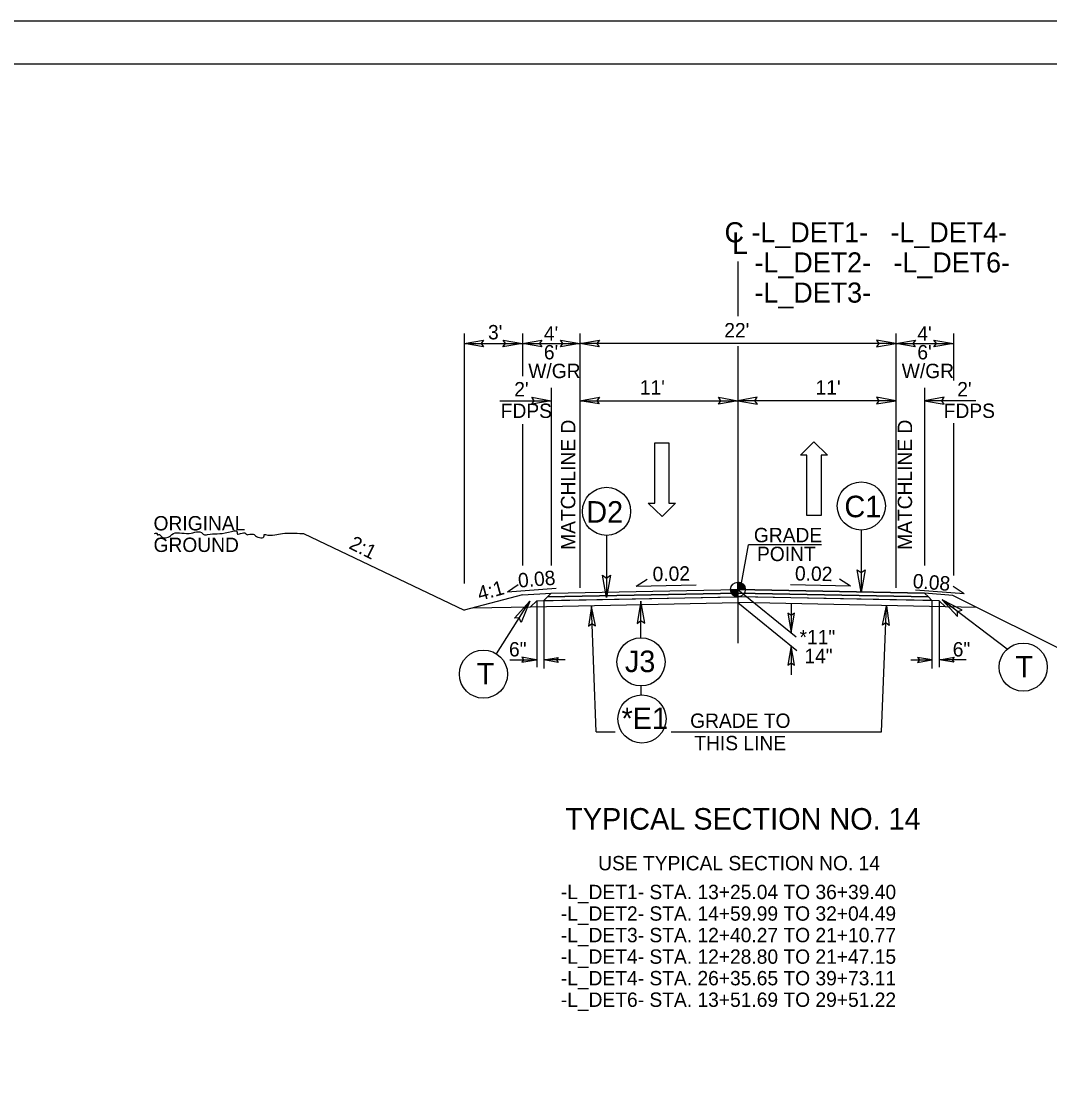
# Model space of a CAD drawing. Extents: x 18938 to 19565, y 6931 to 7973.
# Drawn here: x 19226.8 to 19298.4, y 7150.9 to 7224.2 of the extents above; entities that cross this region are included whole.
import ezdxf

# ---------------------------------------------------------------- set-up
doc = ezdxf.new("R2010")
doc.units = 0
for name, color, linetype in [('Old_Level_11', 7, 'Continuous'), ('Old_Level_2', 7, 'Continuous'), ('Old_Level_3', 7, 'Continuous'), ('Prop Dimension', 7, 'Continuous'), ('Prop Pavement Schedule Description CELL', 7, 'Continuous'), ('Prop Shade Medium', 7, 'Continuous'), ('Prop Terminator CELL', 7, 'Continuous'), ('Sheet Block Title CELL', 7, 'Continuous'), ('Sheet Data Field CELL', 7, 'Continuous'), ('Sheet Plot Border Outside CELL', 7, 'Continuous'), ('Sheet Typical CELL', 7, 'Continuous'), ('Typical Curb CELL', 7, 'Continuous'), ('Typical Detail Wedge1 CELL', 7, 'Continuous'), ('Typical Detail Wedge2 CELL', 7, 'Continuous'), ('Typical Detail Wedge3 CELL', 7, 'Continuous'), ('Typical Hinge Slope Arterial CELL', 7, 'Continuous'), ('Typical Pavement Slope Information CELL', 7, 'Continuous'), ('Typical Shoulder Slope Information CELL', 7, 'Continuous'), ('Typical Terminator CELL', 7, 'Continuous'), ('Typical Text General CELL', 7, 'Continuous'), ('Typical Text Grade Point CELL', 7, 'Continuous'), ('Typical Text ID Circle CELL', 7, 'Continuous'), ('Typical Text Label CELL', 7, 'Continuous')]:
    doc.layers.add(name, color=color, linetype=linetype)

msp = doc.modelspace()

# ---------------------------------------------------------------- linework, layer by layer
at = {"layer": 'Old_Level_3'}
for p, q in [((19260.819, 7179.737), (19262.657, 7179.733)), ((19260.819, 7179.737), (19262.657, 7179.733)), ((19264.664, 7179.722), (19263.187, 7179.722)), ((19264.664, 7179.722), (19263.187, 7179.722)), ((19288.731, 7179.722), (19290.208, 7179.722)), ((19292.576, 7179.737), (19290.738, 7179.733))]:
    msp.add_line(p, q, dxfattribs=at)
at = {"layer": 'Prop Dimension'}
msp.add_lwpolyline([(19155.167, 7077.771), (19382.434, 7077.771), (19382.434, 7224.204), (19155.167, 7224.204)], close=True, dxfattribs=at)
at = {"layer": 'Prop Pavement Schedule Description CELL'}
for p, q in [((19261.697, 7184.244), (19263.697, 7184.366)), ((19262.687, 7183.846), (19276.442, 7184.121)), ((19262.687, 7183.846), (19276.442, 7184.121)), ((19263.442, 7184.111), (19276.697, 7184.376)), ((19263.442, 7184.111), (19263.697, 7184.366)), ((19263.697, 7184.366), (19276.698, 7184.626)), ((19289.697, 7184.366), (19276.697, 7184.626)), ((19289.953, 7184.111), (19276.697, 7184.376)), ((19290.708, 7183.846), (19276.953, 7184.121)), ((19291.66, 7184.209), (19289.697, 7184.366)), ((19289.953, 7184.111), (19289.697, 7184.366)), ((19308.052, 7176.014), (19291.66, 7184.209)), ((19258.223, 7183.341), (19262.254, 7183.421)), ((19262.254, 7183.421), (19262.687, 7183.846)), ((19262.254, 7183.421), (19262.687, 7183.846)), ((19262.254, 7183.421), (19276.711, 7183.711)), ((19291.141, 7183.421), (19276.684, 7183.711)), ((19291.141, 7183.421), (19290.708, 7183.846)), ((19293.323, 7183.378), (19291.141, 7183.421))]:
    msp.add_line(p, q, dxfattribs=at)
at = {"layer": 'Prop Shade Medium'}
for p in [(19246.456, 7188.533), (19261.697, 7184.244)]:
    msp.add_line(p, (19257.631, 7183.187), dxfattribs=at)
at = {"layer": 'Sheet Block Title CELL'}
for p, q in [((19263.187, 7183.856), (19276.697, 7184.126)), ((19263.187, 7183.856), (19276.697, 7184.126)), ((19263.442, 7184.111), (19263.187, 7183.856)), ((19263.442, 7184.111), (19263.187, 7183.856)), ((19276.697, 7184.376), (19263.442, 7184.111)), ((19276.697, 7184.376), (19263.442, 7184.111)), ((19276.697, 7184.126), (19276.697, 7184.376)), ((19276.697, 7184.376), (19289.953, 7184.111)), ((19276.698, 7184.126), (19276.697, 7184.376)), ((19276.697, 7184.126), (19276.697, 7184.376)), ((19290.208, 7183.856), (19276.698, 7184.126)), ((19289.953, 7184.111), (19290.208, 7183.856))]:
    msp.add_line(p, q, dxfattribs=at)
at = {"layer": 'Sheet Data Field CELL'}
for points in [[(19258.981, 7201.521), (19257.631, 7201.753), (19258.988, 7201.993), (19258.816, 7201.753)], [(19260.347, 7201.986), (19261.697, 7201.753), (19260.34, 7201.513), (19260.512, 7201.753)], [(19263.047, 7201.521), (19261.697, 7201.753), (19263.055, 7201.993), (19262.882, 7201.753)], [(19264.347, 7201.986), (19265.697, 7201.753), (19264.34, 7201.513), (19264.512, 7201.753)], [(19267.047, 7201.521), (19265.697, 7201.753), (19267.055, 7201.993), (19266.882, 7201.753)], [(19286.347, 7201.521), (19287.697, 7201.753), (19286.34, 7201.993), (19286.512, 7201.753)], [(19289.047, 7201.521), (19287.697, 7201.753), (19289.055, 7201.993), (19288.882, 7201.753)], [(19290.347, 7201.986), (19291.697, 7201.753), (19290.34, 7201.513), (19290.512, 7201.753)], [(19262.347, 7198.007), (19263.697, 7197.774), (19262.34, 7197.534), (19262.512, 7197.774)], [(19267.047, 7197.542), (19265.697, 7197.774), (19267.055, 7198.014), (19266.882, 7197.774)], [(19275.347, 7198.007), (19276.697, 7197.774), (19275.34, 7197.534), (19275.512, 7197.774)], [(19278.047, 7198.007), (19276.697, 7197.774), (19278.055, 7197.534), (19277.882, 7197.774)], [(19286.347, 7197.542), (19287.697, 7197.774), (19286.34, 7198.014), (19286.512, 7197.774)], [(19291.047, 7198.007), (19289.697, 7197.774), (19291.055, 7197.534), (19290.882, 7197.774)], [(19266.773, 7182.101), (19266.495, 7183.443), (19266.301, 7182.078), (19266.535, 7182.259)], [(19286.764, 7182.148), (19287.042, 7183.49), (19287.236, 7182.125), (19287.002, 7182.305)], [(19280.174, 7182.972), (19280.407, 7181.622), (19280.647, 7182.979), (19280.407, 7182.807)], [(19280.639, 7179.356), (19280.407, 7180.706), (19280.167, 7179.348), (19280.407, 7179.521)]]:
    msp.add_lwpolyline(points, close=True, dxfattribs=at)
at = {"layer": 'Sheet Typical CELL'}
for p, q in [((19257.631, 7202.445), (19257.631, 7185.054)), ((19261.697, 7202.445), (19261.697, 7199.487)), ((19265.697, 7202.445), (19265.697, 7184.739)), ((19287.697, 7202.445), (19287.697, 7184.739)), ((19291.697, 7202.445), (19291.697, 7199.174)), ((19257.631, 7201.753), (19261.697, 7201.753)), ((19261.697, 7201.753), (19265.697, 7201.753)), ((19287.697, 7201.753), (19265.697, 7201.753)), ((19287.697, 7201.753), (19291.697, 7201.753)), ((19263.697, 7198.677), (19263.697, 7186.297)), ((19289.697, 7198.677), (19289.697, 7186.297)), ((19260.126, 7197.774), (19263.697, 7197.774)), ((19265.697, 7197.774), (19276.697, 7197.774)), ((19287.697, 7197.774), (19276.697, 7197.774)), ((19293.269, 7197.774), (19289.697, 7197.774)), ((19261.697, 7196.132), (19261.697, 7186.297)), ((19291.697, 7196.204), (19291.697, 7185.594)), ((19276.698, 7184.626), (19280.753, 7181.342)), ((19262.687, 7183.846), (19262.687, 7179.226)), ((19262.687, 7183.846), (19262.687, 7179.226)), ((19263.187, 7183.856), (19263.187, 7179.125)), ((19263.187, 7183.856), (19263.187, 7179.125)), ((19266.836, 7174.714), (19266.495, 7183.443)), ((19276.698, 7183.71), (19280.803, 7180.385)), ((19280.407, 7183.666), (19280.407, 7181.622)), ((19286.697, 7174.714), (19287.04, 7183.503)), ((19290.208, 7183.856), (19290.208, 7179.125)), ((19290.708, 7183.846), (19290.708, 7179.226)), ((19280.407, 7180.706), (19280.407, 7178.682)), ((19269.949, 7177.91), (19269.949, 7177.29)), ((19266.836, 7174.714), (19268.151, 7174.714)), ((19272.044, 7174.714), (19286.697, 7174.714))]:
    msp.add_line(p, q, dxfattribs=at)
at = {"layer": 'Typical Curb CELL'}
msp.add_spline([(19236.091, 7188.533), (19236.263, 7188.533), (19236.263, 7188.447), (19236.434, 7188.447), (19236.52, 7188.361), (19237.205, 7188.361), (19237.29, 7188.447), (19238.49, 7188.533), (19239.432, 7188.533), (19239.517, 7188.447), (19239.775, 7188.447), (19241.231, 7188.618), (19241.83, 7188.618), (19241.83, 7188.533), (19242.43, 7188.533), (19242.515, 7188.447), (19242.601, 7188.447), (19243.029, 7188.447), (19243.115, 7188.361), (19243.714, 7188.361), (19243.714, 7188.447), (19243.8, 7188.447), (19244.999, 7188.533), (19246.37, 7188.533), (19246.456, 7188.533)], degree=3, dxfattribs=at)
at = {"layer": 'Typical Detail Wedge1 CELL'}
for p, q in [((19276.698, 7184.626), (19276.698, 7185.138)), ((19276.185, 7184.626), (19276.698, 7184.626)), ((19276.697, 7184.114), (19276.698, 7184.626)), ((19276.698, 7184.626), (19276.697, 7184.114)), ((19277.209, 7184.626), (19276.698, 7184.626))]:
    msp.add_line(p, q, dxfattribs=at)
for points in [[(19276.702, 7185.138), (19276.702, 7185.138), (19276.702, 7184.626)], [(19276.713, 7185.138), (19276.713, 7184.626)], [(19276.723, 7185.138), (19276.723, 7184.626)], [(19276.733, 7185.137), (19276.733, 7184.626)], [(19276.744, 7185.136), (19276.744, 7184.626)], [(19276.754, 7185.135), (19276.754, 7184.626)], [(19276.764, 7185.134), (19276.764, 7184.626)], [(19276.774, 7185.133), (19276.774, 7184.626)], [(19276.785, 7185.131), (19276.784, 7184.626)], [(19276.795, 7185.129), (19276.795, 7184.626)], [(19276.805, 7185.127), (19276.805, 7184.626)], [(19276.815, 7185.124), (19276.815, 7184.626)], [(19276.826, 7185.122), (19276.825, 7184.626)], [(19276.836, 7185.119), (19276.836, 7184.626)], [(19276.846, 7185.116), (19276.846, 7184.626)], [(19276.856, 7185.113), (19276.856, 7184.626)], [(19276.867, 7185.11), (19276.866, 7184.626)], [(19276.877, 7185.106), (19276.876, 7184.626)], [(19276.887, 7185.102), (19276.887, 7184.626)], [(19276.897, 7185.098), (19276.897, 7184.626)], [(19276.907, 7185.093), (19276.907, 7184.626)], [(19276.918, 7185.089), (19276.918, 7184.626)], [(19276.928, 7185.084), (19276.928, 7184.626)], [(19276.938, 7185.078), (19276.938, 7184.626)], [(19276.949, 7185.073), (19276.948, 7184.626)], [(19276.959, 7185.067), (19276.959, 7184.626)], [(19276.969, 7185.061), (19276.969, 7184.626)], [(19276.979, 7185.054), (19276.979, 7184.626)], [(19276.989, 7185.047), (19276.989, 7184.626)], [(19277, 7185.04), (19277, 7184.626)], [(19277.01, 7185.032), (19277.01, 7184.626)], [(19277.02, 7185.024), (19277.02, 7184.626)], [(19277.03, 7185.015), (19277.03, 7184.626)], [(19277.041, 7185.006), (19277.04, 7184.626)], [(19277.051, 7184.997), (19277.051, 7184.626)], [(19277.061, 7184.987), (19277.061, 7184.626)], [(19277.071, 7184.976), (19277.071, 7184.626)], [(19277.081, 7184.965), (19277.081, 7184.626)], [(19277.092, 7184.953), (19277.092, 7184.626)], [(19277.102, 7184.94), (19277.102, 7184.626)], [(19277.112, 7184.927), (19277.112, 7184.626)], [(19277.122, 7184.912), (19277.122, 7184.626)], [(19277.133, 7184.896), (19277.133, 7184.626)], [(19277.143, 7184.879), (19277.143, 7184.626)], [(19277.153, 7184.86), (19277.153, 7184.626)], [(19277.164, 7184.838), (19277.163, 7184.626)], [(19276.188, 7184.626), (19276.188, 7184.57)], [(19276.199, 7184.626), (19276.199, 7184.51)], [(19276.209, 7184.626), (19276.209, 7184.473)], [(19276.219, 7184.626), (19276.219, 7184.444)], [(19276.229, 7184.626), (19276.229, 7184.418)], [(19276.24, 7184.626), (19276.24, 7184.397)], [(19276.25, 7184.626), (19276.25, 7184.377)], [(19276.26, 7184.626), (19276.26, 7184.36)], [(19276.271, 7184.626), (19276.271, 7184.344)], [(19276.281, 7184.626), (19276.281, 7184.329)], [(19276.291, 7184.626), (19276.291, 7184.315)], [(19276.301, 7184.626), (19276.301, 7184.302)], [(19276.311, 7184.626), (19276.311, 7184.29)], [(19276.322, 7184.626), (19276.322, 7184.278)], [(19276.332, 7184.626), (19276.332, 7184.268)], [(19276.342, 7184.626), (19276.342, 7184.258)], [(19276.352, 7184.626), (19276.352, 7184.248)], [(19276.363, 7184.626), (19276.362, 7184.239)], [(19276.373, 7184.626), (19276.373, 7184.23)], [(19276.383, 7184.626), (19276.383, 7184.222)], [(19276.393, 7184.626), (19276.393, 7184.215)], [(19276.403, 7184.626), (19276.403, 7184.207)], [(19276.414, 7184.626), (19276.414, 7184.2)], [(19276.424, 7184.626), (19276.424, 7184.193)], [(19276.434, 7184.626), (19276.434, 7184.187)], [(19276.445, 7184.626), (19276.445, 7184.181)], [(19276.455, 7184.626), (19276.455, 7184.175)], [(19276.465, 7184.626), (19276.465, 7184.17)], [(19276.475, 7184.626), (19276.475, 7184.165)], [(19276.486, 7184.626), (19276.485, 7184.161)], [(19276.496, 7184.626), (19276.496, 7184.156)], [(19276.506, 7184.626), (19276.506, 7184.152)], [(19276.516, 7184.626), (19276.516, 7184.147)], [(19276.527, 7184.626), (19276.527, 7184.144)], [(19276.537, 7184.626), (19276.537, 7184.14)], [(19276.547, 7184.626), (19276.547, 7184.137)], [(19276.557, 7184.626), (19276.557, 7184.134)], [(19276.567, 7184.626), (19276.567, 7184.131)], [(19276.578, 7184.626), (19276.577, 7184.129)], [(19276.588, 7184.626), (19276.588, 7184.126)], [(19276.598, 7184.626), (19276.598, 7184.124)], [(19276.608, 7184.626), (19276.608, 7184.122)], [(19276.618, 7184.626), (19276.618, 7184.121)], [(19276.629, 7184.626), (19276.629, 7184.119)], [(19276.639, 7184.626), (19276.639, 7184.118)], [(19276.649, 7184.626), (19276.649, 7184.116)], [(19276.66, 7184.626), (19276.66, 7184.116)], [(19276.67, 7184.626), (19276.67, 7184.115)], [(19276.68, 7184.626), (19276.68, 7184.115)], [(19276.69, 7184.626), (19276.69, 7184.114), (19276.69, 7184.114)], [(19277.174, 7184.815), (19277.174, 7184.626)], [(19277.184, 7184.786), (19277.184, 7184.626)], [(19277.194, 7184.751), (19277.194, 7184.626)], [(19277.204, 7184.699), (19277.204, 7184.626)]]:
    msp.add_lwpolyline(points, dxfattribs=at)
msp.add_circle((19276.697, 7184.626), 0.512, dxfattribs=at)
for start, end in [(359.99048, 89.99048), (179.99048, 269.99048)]:
    msp.add_arc((19276.697, 7184.626), 0.512, start, end, dxfattribs=at)
at = {"layer": 'Typical Detail Wedge3 CELL'}
for p, q in [((19270.905, 7190.645), (19270.905, 7194.845)), ((19270.905, 7194.845), (19271.895, 7194.845)), ((19271.895, 7194.845), (19271.895, 7190.645)), ((19281.05, 7193.974), (19281.98, 7194.919)), ((19281.98, 7194.919), (19282.94, 7193.974)), ((19281.5, 7193.974), (19281.05, 7193.974)), ((19281.5, 7189.774), (19281.5, 7193.974)), ((19282.94, 7193.974), (19282.49, 7193.974)), ((19282.49, 7193.974), (19282.49, 7189.774)), ((19271.415, 7189.7), (19270.455, 7190.645)), ((19270.455, 7190.645), (19270.905, 7190.645)), ((19272.345, 7190.645), (19271.415, 7189.7)), ((19271.895, 7190.645), (19272.345, 7190.645)), ((19282.49, 7189.774), (19281.5, 7189.774))]:
    msp.add_line(p, q, dxfattribs=at)
at = {"layer": 'Typical Hinge Slope Arterial CELL'}
for p, q in [((19263.442, 7184.111), (19263.697, 7184.366)), ((19263.697, 7184.116), (19263.442, 7184.111)), ((19263.697, 7184.366), (19276.698, 7184.626)), ((19276.698, 7184.376), (19263.697, 7184.116)), ((19263.697, 7184.116), (19263.697, 7184.116)), ((19276.698, 7184.626), (19289.697, 7184.366)), ((19289.953, 7184.111), (19276.698, 7184.376)), ((19289.697, 7184.366), (19289.953, 7184.111))]:
    msp.add_line(p, q, dxfattribs=at)
at = {"layer": 'Typical Pavement Slope Information CELL'}
msp.add_lwpolyline([(19380.142, 7221.197), (19177.642, 7221.197), (19177.642, 7080.781), (19380.142, 7080.781)], close=True, dxfattribs=at)
at = {"layer": 'Typical Terminator CELL'}
for p, q in [((19285.285, 7188.769), (19285.285, 7184.438)), ((19267.551, 7188.392), (19267.551, 7184.061)), ((19259.882, 7180.151), (19262.208, 7183.804)), ((19269.949, 7181.262), (19269.949, 7183.825)), ((19295.435, 7180.465), (19290.908, 7183.918))]:
    msp.add_line(p, q, dxfattribs=at)
for centre in [(19267.551, 7190.068), (19285.285, 7190.445), (19269.949, 7179.586), (19296.558, 7179.222), (19258.982, 7178.737), (19270.017, 7175.615)]:
    msp.add_circle(centre, 1.676, dxfattribs=at)
at = {"layer": 'Typical Text General CELL'}
for points in [[(19267.819, 7185.613), (19267.551, 7184.061), (19267.276, 7185.621), (19267.551, 7185.423)], [(19285.553, 7185.99), (19285.285, 7184.438), (19285.01, 7185.999), (19285.285, 7185.8)], [(19261.149, 7182.639), (19262.208, 7183.804), (19261.603, 7182.34), (19261.477, 7182.655)], [(19270.217, 7182.273), (19269.949, 7183.825), (19269.673, 7182.265), (19269.949, 7182.463)], [(19292.304, 7183.19), (19290.908, 7183.918), (19291.981, 7182.752), (19291.991, 7183.092)], [(19261.659, 7179.561), (19262.657, 7179.733), (19261.654, 7179.91), (19261.781, 7179.733)], [(19261.659, 7179.561), (19262.657, 7179.733), (19261.654, 7179.91), (19261.781, 7179.733)], [(19264.185, 7179.55), (19263.187, 7179.722), (19264.19, 7179.899), (19264.063, 7179.722)], [(19264.185, 7179.55), (19263.187, 7179.722), (19264.19, 7179.899), (19264.063, 7179.722)], [(19289.21, 7179.55), (19290.208, 7179.722), (19289.205, 7179.899), (19289.332, 7179.722)], [(19291.736, 7179.561), (19290.738, 7179.733), (19291.741, 7179.91), (19291.614, 7179.733)]]:
    msp.add_lwpolyline(points, close=True, dxfattribs=at)
at = {"layer": 'Typical Text Grade Point CELL'}
for p, q in [((19260.648, 7184.455), (19261.401, 7184.974)), ((19269.602, 7184.867), (19270.385, 7185.34)), ((19269.602, 7184.867), (19273.79, 7184.95)), ((19284.546, 7184.867), (19280.357, 7184.95)), ((19284.546, 7184.867), (19283.763, 7185.34)), ((19292.443, 7184.32), (19291.69, 7184.84)), ((19260.648, 7184.455), (19264.034, 7184.726)), ((19292.443, 7184.32), (19289.058, 7184.591))]:
    msp.add_line(p, q, dxfattribs=at)
at = {"layer": 'Typical Text ID Circle CELL'}
for p, q in [((19276.683, 7207.456), (19276.683, 7203.661)), ((19276.697, 7201.571), (19276.697, 7180.89)), ((19276.948, 7185.079), (19277.443, 7187.747)), ((19282.52, 7187.747), (19277.443, 7187.747))]:
    msp.add_line(p, q, dxfattribs=at)

# ---------------------------------------------------------------- texts
at = {"layer": 'Old_Level_11'}
for s, height, p in [('TYPICAL SECTION NO. 14', 1.5, (19264.674, 7167.907)), ('USE TYPICAL SECTION NO. 14', 1, (19266.969, 7165.073))]:
    msp.add_text(s, height=height, dxfattribs=at).set_placement(p)
at = {"layer": 'Old_Level_2'}
for s, p in [('ORIGINAL', (19236.015, 7188.739)), ('GROUND', (19236.015, 7187.239))]:
    msp.add_text(s, height=1, rotation=360, dxfattribs=at).set_placement(p)
at = {"layer": 'Old_Level_3'}
for p in [(19260.761, 7179.964), (19260.761, 7179.964), (19291.651, 7179.964)]:
    msp.add_text('6"', height=1, dxfattribs=at).set_placement(p)
at = {"layer": 'Prop Terminator CELL'}
for s, p in [('D2', (19266.141, 7189.279)), ('C1', (19284.112, 7189.657)), ('T', (19296.014, 7178.502))]:
    msp.add_text(s, height=1.5, dxfattribs=at).set_placement(p)
for s, p in [('J3', (19268.83, 7178.874)), ('T', (19258.513, 7178.017)), ('*E1', (19268.593, 7174.904))]:
    msp.add_text(s, height=1.5, rotation=360, dxfattribs=at).set_placement(p)
at = {"layer": 'Sheet Plot Border Outside CELL'}
for s, p in [('GRADE', (19277.808, 7187.916)), ('POINT', (19278.026, 7186.605))]:
    msp.add_text(s, height=1, rotation=0.00004, dxfattribs=at).set_placement(p)
at = {"layer": 'Typical Detail Wedge2 CELL'}
for s, p in [("22'", (19275.748, 7202.179)), ("3'", (19259.301, 7202.043)), ("4'", (19263.188, 7201.953)), ("4'", (19289.188, 7201.953)), ("6' ", (19263.188, 7200.649)), ("6' ", (19289.188, 7200.649)), ('W/GR', (19262.103, 7199.344)), ('W/GR', (19288.103, 7199.344)), ("2'", (19261.126, 7198.071)), ("11'", (19269.868, 7198.2)), ("11'", (19282.107, 7198.2)), ("2'", (19291.965, 7198.071)), ('FDPS', (19260.186, 7196.571)), ('FDPS', (19291.025, 7196.571)), ('*11"', (19280.988, 7180.807)), ('14"', (19281.324, 7179.496)), ('GRADE TO', (19273.371, 7174.992)), ('THIS LINE', (19273.662, 7173.436)), ('-L_DET1- STA. 13+25.04 TO 36+39.40', (19264.368, 7163.067)), ('-L_DET2- STA. 14+59.99 TO 32+04.49', (19264.368, 7161.567)), ('-L_DET3- STA. 12+40.27 TO 21+10.77', (19264.368, 7160.067)), ('-L_DET4- STA. 12+28.80 TO 21+47.15', (19264.368, 7158.567)), ('-L_DET4- STA. 26+35.65 TO 39+73.11', (19264.368, 7157.067)), ('-L_DET6- STA. 13+51.69 TO 29+51.22', (19264.368, 7155.567))]:
    msp.add_text(s, height=1, dxfattribs=at).set_placement(p)
for p in [(19265.377, 7187.387), (19288.821, 7187.387)]:
    msp.add_text('MATCHLINE D', height=1, rotation=90, dxfattribs=at).set_placement(p)
at = {"layer": 'Typical Shoulder Slope Information CELL'}
for s, rotation, p in [('2:1', 333.43491, (19249.553, 7187.516)), ('4:1', 15.1346, (19258.715, 7183.831))]:
    msp.add_text(s, height=1, rotation=rotation, dxfattribs=at).set_placement(p)
at = {"layer": 'Typical Text Grade Point CELL'}
for s, rotation, p in [('0.08', 4.5738, (19261.429, 7184.756)), ('0.02', 1.14574, (19270.769, 7185.201)), ('0.02', 358.85426, (19280.661, 7185.256)), ('0.08', 355.4262, (19288.84, 7184.734))]:
    msp.add_text(s, height=1, rotation=rotation, dxfattribs=at).set_placement(p)
at = {"layer": 'Typical Text Label CELL'}
for s, height, p in [('C -L_DET1-   -L_DET4-', 1.4, (19275.769, 7208.799)), ('L', 1.5, (19276.285, 7207.992)), ('    -L_DET2-   -L_DET6-', 1.4, (19275.769, 7206.699)), ('    -L_DET3-   ', 1.4, (19275.769, 7204.599))]:
    msp.add_text(s, height=height, dxfattribs=at).set_placement(p)

doc.saveas('drawing.dxf')
